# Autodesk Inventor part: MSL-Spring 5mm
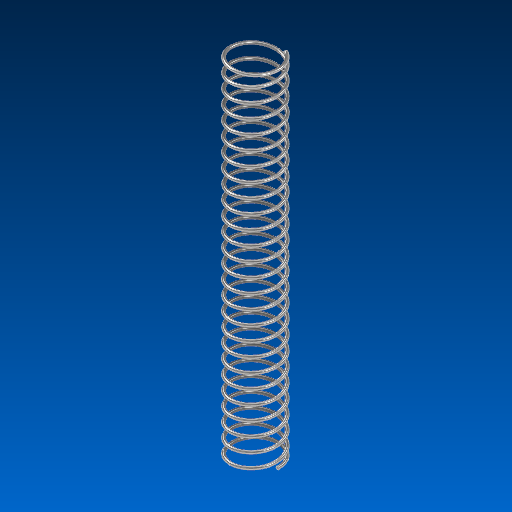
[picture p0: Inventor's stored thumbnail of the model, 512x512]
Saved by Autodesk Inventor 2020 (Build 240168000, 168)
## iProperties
Created: 2019-08
Part Number: MSL-Spring 5mm
Material: Stainless Steel
Document SubType Name: Modeling
Designer: J. Nielson
Density: 8 g/cm^3
Appearance: Semi-Polished
Author: J. Nielson
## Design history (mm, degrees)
sketch "Sketch1"
  geometry: L1 (-2.5, 26.403)-(2.5, 26.403) reference; L2 (4, -3.254)-(-4, -3.254) reference; L3 (0, -3.254)-(0, 26.403); C1 r 0.127 at (1.905, -3.127); 1 further point
  constraints: 2 end point, 2 midpoint, 1 centre point, 1 tangent
  dimensions: "d0" = 0.254 diameter of C1; "d1" = 1.905 distance from line of C1.centre L3; "d2" = 29.6574 distance of L3.start L3.end (derived)
coil "Coil1" sketch "Sketch1" pitch "d3" = 25.4; turns "d5" = 25; dims "d4" = 29.4034 (= d2 - d0), "d6" = 0, angle "d7" = 30 deg, angle "d8" = 180 deg, "d9" = 30 deg, "d10" = 180 deg
body "Solid1"
node "Reference1"
node "Reference2"
